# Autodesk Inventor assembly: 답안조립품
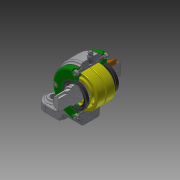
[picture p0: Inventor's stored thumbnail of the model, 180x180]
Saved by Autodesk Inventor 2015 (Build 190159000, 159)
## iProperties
Created: 2019-05
Part Number: 답안조립품
Document SubType Name: Assembly
Designer: CAD02
Author: CAD02
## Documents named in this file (13)
- C:\Users\CAD02\Desktop\490504V1030\답안조립품.iam
- C:\Users\CAD02\Desktop\490504V1030\개스킷.ipt
- C:\Users\CAD02\Desktop\490504V1030\그리스니플 M6.ipt
- 그리스니플  M6.ipt
- C:\Users\CAD02\Desktop\490504V1030\그리스니플개스킷.ipt
- C:\Users\CAD02\Desktop\490504V1030\베어링너트.ipt
- C:\Users\CAD02\Desktop\490504V1030\본체.ipt
- C:\Users\CAD02\Desktop\490504V1030\볼트 M4.ipt
- C:\Users\CAD02\Desktop\490504V1030\앵귤러 볼 베어링 7205.ipt
- C:\Users\CAD02\Desktop\490504V1030\오일 실 28 40 5 B.ipt
- C:\Users\CAD02\Desktop\490504V1030\축.ipt
- C:\Users\CAD02\Desktop\490504V1030\칼라.ipt
- C:\Users\CAD02\Desktop\490504V1030\커버.ipt
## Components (4 placed, 3 different names)
1. 개스킷:1
2. 그리스니플  M6:1
3. 그리스니플개스킷:1
4. 개스킷:2
